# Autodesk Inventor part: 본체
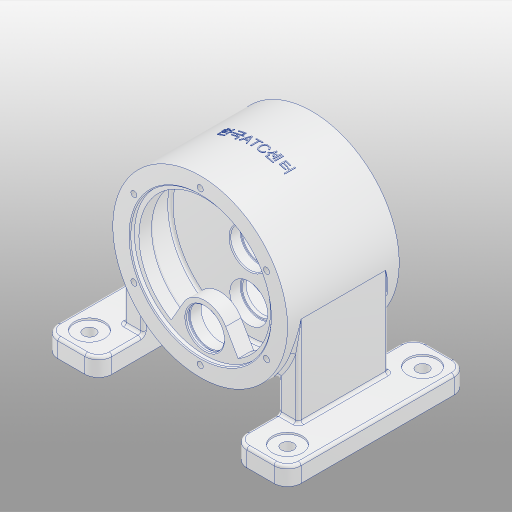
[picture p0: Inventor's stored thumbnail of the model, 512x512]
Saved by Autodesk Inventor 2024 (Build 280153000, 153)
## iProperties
Created: 2025-12
Part Number: 본체
Material: 알루미늄 6061
Document SubType Name: Modeling
Designer: Edu09
Density: 2.7 g/cm^3
Appearance: 알루미늄 - 평지
Mass: 5627.04 g
Surface Area: 3058.5 cm^2
Volume: 2084.09 cm^3
Author: Edu09
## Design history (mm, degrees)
sketch "스케치1"
  geometry: C1 r 97 at (0, 0); 1 further point
  constraints: 1 centre point, 1 coincident
  dimensions: "d0" = 194 diameter of C1
extrude "돌출1" new body sketch "스케치1" stored distance "d1" = 124; taper "d2" = 0 deg
node "작업 평면1"
sketch "스케치2"
  geometry: L1 (135, 100)-(-135, 100); L2 (-135, 100)-(-135, -100); L3 (-135, -100)-(135, -100); L4 (135, -100)-(135, 100); L5 (135, 100)-(-135, -100); L6 (-135, 100)-(135, -100); 1 further point
  constraints: 12 end point, 2 midpoint, 2 parallel, 1 horizontal, 1 perpendicular
  dimensions: "d4" = 200 distance of L1.end L2.end; "d5" = 270 distance of L1.start L1.end
extrude "돌출2" join sketch "스케치2" distance "d6" = 20; taper "d7" = 0 deg
sketch "스케치3"
  geometry: L1 (135, -100)-(135, 100) reference; L2 (-135, 100)-(-135, -100) reference; L3 (-97, -50)-(97, -50); L4 (97, -50)-(97, 50); L5 (97, 50)-(-97, 50); L6 (-97, 50)-(-97, -50); L7 (-97, -50)-(97, 50); L8 (97, -50)-(-97, 50); 1 further point
  constraints: 12 end point, 2 midpoint, 2 parallel, 1 horizontal, 1 perpendicular
  dimensions: "d8" = 38 distance between parallel lines of L1 L4; "d9" = 38 distance between parallel lines of L2 L6 (derived); "d10" = 100 distance of L3.end L4.end
extrude "돌출3" join sketch "스케치3" stored distance "d11" = 20; taper "d12" = 0 deg
sketch "스케치4"
  geometry: L1 (0, 0)-(270, 0) reference; L2 (38, 20)-(38, 120) reference; L3 (232, 20)-(38, 20) reference; L4 (232, 20)-(232, 120) reference; L5 (60, 0)-(60, 58.486); L6 (210, 0)-(210, 58.486); C1 r 97 at (135, 120) reference; A1 r 97 centre (135, 120) between (38, 120) and (232, 120) reference; 3 further points
  constraints: 4 end point, 2 point on circle, 2 point on line, 2 vertical, 1 parallel
  dimensions: "d13" = 150 distance between parallel lines of L5 L6
extrude "돌출4" cut sketch "스케치4" extent not by distance; stored distance "d14" = 0; taper "d15" = 0 deg
sketch "스케치5"
  geometry: L1 (-97, -100)-(-75, -100) reference; L2 (-75, -61.514)-(-75, -100) reference; L3 (75, -100)-(75, -61.514) reference; L4 (-36.6, -89.83)-(-75, -112); L5 (-75, -120)-(-135, -120) reference; L6 (-75, -100)-(-75, -120) reference; A1 r 97 centre (0, 0) between (-75, -61.514) and (75, -61.514) reference; 1 further point
  constraints: 2 end point, 1 point on circle, 1 point on line
  dimensions: "d16" = 60 deg angle of L2 L4; "d17" = 8 distance from line of L4.end L5
extrude "돌출5" join sketch "스케치5" stored distance "d18" = 12; taper "d19" = 0 deg
fillet "모깎기1" dims "d20" = 15
sketch "스케치6"
  geometry: L1 (75, 85)-(75, 50) reference; L2 (75, 50)-(97, 50) reference; L3 (97, 50)-(97, -50) reference; L4 (97, -50)-(75, -50) reference; L5 (75, -50)-(75, -85) reference; L6 (90, -100)-(120, -100) reference; L7 (135, -85)-(135, 85) reference; L8 (120, 100)-(90, 100) reference; L9 (-110, -75)-(110, -75); L10 (110, -75)-(110, 75); L11 (110, 75)-(-110, 75); L12 (-110, 75)-(-110, -75); L13 (-110, -75)-(110, 75); L14 (110, -75)-(-110, 75); A1 r 15 centre (90, 85) between (90, 100) and (75, 85) reference; A2 r 15 centre (90, -85) between (75, -85) and (90, -100) reference; A3 r 15 centre (120, -85) between (120, -100) and (135, -85) reference; A4 r 15 centre (120, 85) between (135, 85) and (120, 100) reference; 1 further point
  constraints: 12 end point, 2 midpoint, 2 parallel, 1 horizontal, 1 perpendicular
  dimensions: "d21" = 150 distance of L9.end L10.end; "d22" = 220 distance of L10.end L11.end
hole "구멍1" sketch "스케치6" at (-110, 75), (-110, -75), (110, -75), (110, 75) diameter "d23" = 13.5; stored, may be unused: countersink angle "d27" = 90 deg, drill point angle "d29" = 118 deg; dims "d24" = 6, "d25" = 33, "d26" = 2, "d28" = 8
sketch "스케치7"
  geometry: L1 (97, 62)-(-97, 62) reference; L2 (-97, -62)-(97, -62) reference; L3 (0, 62)-(0, -62); L4 (78, -62)-(78, -57); L5 (78, -57)-(73, -57); L6 (73, -57)-(73, -40); L7 (73, -40)-(87, -40); L8 (87, -40)-(87, -8); L9 (87, -8)-(0, -8); 1 further point
  constraints: 14 end point, 5 perpendicular, 2 midpoint, 2 point on line, 1 vertical
  dimensions: "d30" = 174 diameter of L8 L3; "d31" = 156 diameter of L4 L3; "d32" = 146 diameter of L6 L3; "d33" = 32 distance of L7.end L8.end; "d34" = 22 distance between parallel lines of L2 L7; "d35" = 5 distance of L4.start L4.end
revolve "회전1" sketch "스케치7" stored, may be unused: angle "d36" = 90 deg
sketch "스케치9"
  geometry: L1 (97, 62)-(-97, 62) reference; L2 (78, -62)-(-78, -62) reference; L3 (0, 62)-(0, -62); L4 (87, -8)-(-87, -8) reference; L5 (19, -8)-(19, -4); L6 (19, -4)-(21, -4); L7 (21, -4)-(21, 8); L8 (21, 8)-(0, 8); 2 further points
  constraints: 10 end point, 3 perpendicular, 2 midpoint, 2 point on line, 1 vertical
  dimensions: "d37" = 42 diameter of L7 L3; "d38" = 38 diameter of L5 L3; "d39" = 66 distance between parallel lines of L1 L6; "d40" = 54 distance between parallel lines of L1 L8
revolve "회전2" sketch "스케치9" stored, may be unused: angle "d41" = 90 deg
sketch "스케치10"
  geometry: L1 (97, 62)-(-97, 62) reference; L2 (78, -62)-(-78, -62) reference; L3 (-52.5, 62)-(-52.5, -62); L4 (87, -8)-(-87, -8) reference; L5 (-33.5, -8)-(-33.5, -4); L6 (-33.5, -4)-(-31.5, -4); L7 (-31.5, -4)-(-31.5, 8); L8 (-31.5, 8)-(-52.5, 8); L9 (21, 8)-(-21, 8) reference; L10 (19, -4)-(-19, -4) reference; 2 further points
  constraints: 10 end point, 4 perpendicular, 4 point on line, 2 collinear, 1 vertical
  dimensions: "d42" = 52.5 horizontal distance of L3.start point (0, 0); "d43" = 42 diameter of L7 L3; "d44" = 38 diameter of L5 L3
revolve "회전3" sketch "스케치10" stored, may be unused: angle "d45" = 90 deg
sketch "스케치11"
  geometry: L1 (97, 62)-(-97, 62) reference; L2 (78, -62)-(-78, -62) reference; L3 (0, 62)-(0, -62); L4 (21, 8)-(-21, 8) reference; L5 (0, 8)-(87, 8); L6 (87, 8)-(87, 40); L7 (87, 40)-(0, 40); 3 further points
  constraints: 8 end point, 3 midpoint, 2 perpendicular, 1 horizontal, 1 point on line
  dimensions: "d46" = 32 distance of L5.end L6.end; "d47" = 22 distance between parallel lines of L1 L7 (derived); "d48" = 174 diameter of L6 L3
revolve "회전4" sketch "스케치11" stored, may be unused: angle "d49" = 90 deg
sketch "스케치12"
  geometry: L1 (97, 62)-(-97, 62) reference; L2 (0, 62)-(0, -62); L3 (78, -62)-(-78, -62) reference; L4 (0, 57)-(78, 57); L5 (78, 57)-(78, 62); 1 further point
  constraints: 6 end point, 2 midpoint, 2 point on line, 1 horizontal, 1 perpendicular
  dimensions: "d50" = 156 diameter of L5 L2; "d51" = 5 distance of L4.end L5.end
revolve "회전5" sketch "스케치12" stored, may be unused: angle "d52" = 90 deg
sketch "스케치13"
  geometry: L1 (-23.383, -39)-(-37.148, -62.842); L2 (23.383, -39)-(37.148, -62.842); L3 (0, 0)-(0, -97); C1 r 78 at (0, 0) reference; A1 r 73 centre (0, 0) between (-37.148, -62.842) and (37.148, -62.842); A2 r 27 centre (0, -52.5) between (-23.383, -39) and (23.383, -39); 1 further point
  constraints: 6 end point, 4 point on circle, 2 centre point, 2 tangent, 2 vertical alignment, 1 coincident, 1 vertical, 1 other
  dimensions: "d53" = 146 diameter of A1; "d54" = 30 deg angle of L3 L2; "d55" = 30 deg angle of L3 L1; "d56" = 54 diameter of A2; "d57" = 52.5 distance of A2.centre C1.centre
extrude "돌출6" cut sketch "스케치13" stored distance "d58" = 12; taper "d59" = 0 deg
sketch "스케치14"
  geometry: L1 (-78, 62)-(78, 62) reference; L2 (78, -62)-(-78, -62) reference; L3 (-52.5, 62)-(-52.5, -62); L4 (-62.842, 57)-(73, 57) reference; L5 (-31.5, 57)-(-31.5, 53.95); L6 (-31.5, 53.95)-(-30.25, 53.95); L7 (-30.25, 53.95)-(-30.25, 52); L8 (-30.25, 52)-(-31.5, 52); L9 (-31.5, 52)-(-31.5, 40); L10 (-39, 40)-(-25.5, 40) reference; L11 (-62.842, 40)-(-39, 40) reference; 3 further points
  constraints: 12 end point, 4 point on line, 3 perpendicular, 1 horizontal, 1 vertical
  dimensions: "d60" = 52.5 distance from line of L3 point (0, 0); "d61" = 44.5 diameter of L7 L3; "d62" = 42 diameter of L5 L3; "d63" = 42 diameter of L9 L3; "d64" = 12 distance between parallel lines of L8 L11; "d65" = 1.95 distance of L6.end L7.end
revolve "회전6" sketch "스케치14" stored, may be unused: angle "d66" = 90 deg
fillet "모깎기2" dims "d67" = 0.6
chamfer "모따기1" distance "d68" = 1; stored, may be unused: second distance "d69" = 2, angle "d70" = 45 deg
fillet "모깎기3" dims "d71" = 3
fillet "모깎기4" dims "d72" = 3
fillet "모깎기5" dims "d73" = 3
fillet "모깎기7" dims "d75" = 3
fillet "모깎기8" dims "d76" = 3
fillet "모깎기9" dims "d77" = 3
fillet "모깎기10" dims "d78" = 3
fillet "모깎기11" dims "d79" = 3
fillet "모깎기12" dims "d80" = 3
fillet "모깎기13" dims "d81" = 3
fillet "모깎기14" dims "d82" = 3
fillet "모깎기15" dims "d83" = 3
fillet "모깎기16" dims "d84" = 3
sketch "스케치15"
  geometry: L1 (0, 0)-(0, 85); C1 r 79 at (0, 0) reference
  constraints: 2 end point, 1 vertical
  dimensions: "d85" = 85 distance of L1.start L1.end
hole "구멍2" sketch "스케치15" at (0, 85) diameter "d86" = 6.647; stored, may be unused: countersink angle "d90" = 90 deg, drill point angle "d92" = 118 deg; dims "d87" = 16, "d88" = 4, "d89" = 2, "d91" = 18
sketch "스케치16"
  geometry: 2 further points
  constraints: 1 coincident, 1 other
feature "엠보싱1" sketch "스케치16" dims "d8" = 38, "d9" = 38 (derived), "d10" = 100, "d96" = 0.5, "d97" = 0
node "솔리드1"
mirror "미러1"
pattern_circular "원형 패턴1" dims angle "d94" = 360 deg
mirror "미러2"
node "투영된 루프1"
node "투영된 루프2"
node "투영된 루프3"
node "투영된 루프4"
feature "A9D066F2-1C7D-4E18-AEED-F7BC21143FA4" dims "d86" = 6.647, "d87" = 16, "d88" = 4, "d89" = 2, "d90" = 90 deg, "d91" = 18, "d92" = 118 deg
